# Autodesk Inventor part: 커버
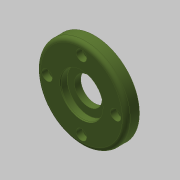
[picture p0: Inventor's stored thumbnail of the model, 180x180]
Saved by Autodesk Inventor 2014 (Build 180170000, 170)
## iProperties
Created: 2016-06
Part Number: 커버
Material: 알루미늄 6061
Document SubType Name: Modeling
Designer: mduedu
Density: 2.71 g/cm^3
Appearance: 올리브 녹색
Author: mduedu
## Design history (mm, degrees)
sketch "스케치1"
  geometry: C1 r 34 at (0, 0); 1 further point
  constraints: 1 centre point, 1 coincident
  dimensions: "d0" = 68 diameter of C1
extrude "돌출1" new body sketch "스케치1" distance "d2" = 10; taper "d3" = 0 deg
sketch "스케치2"
  geometry: C1 r 21 at (0, 0); 1 further point
  constraints: 1 centre point, 1 coincident
  dimensions: "d4" = 42 diameter of C1
extrude "돌출2" join sketch "스케치2" distance "d6" = 3; taper "d7" = 0 deg
fillet "모깎기1" dims "d8" = 3
hole "구멍1" diameter "d11" = 35; stored, may be unused: countersink angle "d15" = 90 deg, drill point angle "d17" = 0 deg; dims "d9" = 10, "d10" = 10, "d12" = 6, "d13" = 4, "d14" = 2, "d16" = 3
hole "구멍2" diameter "d20" = 32; stored, may be unused: countersink angle "d24" = 90 deg, drill point angle "d26" = 0 deg; dims "d21" = 6, "d22" = 4, "d23" = 2, "d25" = 5.2, "d46" = 10, "d47" = 10
hole "구멍3" diameter "d29" = 21; stored, may be unused: countersink angle "d33" = 90 deg, drill point angle "d35" = 0 deg; dims "d27" = 10, "d28" = 10, "d30" = 6, "d31" = 4, "d32" = 2, "d34" = 5
fillet "모깎기2" dims "d36" = 3
fillet "모깎기3" dims "d37" = 0.1
chamfer "모따기1" distance "d38" = 0.75; stored, may be unused: second distance "d39" = 2, angle "d40" = 30 deg
chamfer "모따기2" distance "d42" = 0.5; stored, may be unused: second distance "d43" = 2, angle "d44" = 30 deg
sketch "스케치3" dims "d48" = 52
  geometry: 6 further points
  constraints: 2 vertical alignment, 1 coincident, 7 other
  dimensions: "d51" = 360 deg dimension on point (0, 0) point (0, 26) (derived)
sketch "스케치4"
  geometry: 4 further points
hole "구멍4" sketch "스케치4" at (0, 26), (-26, 0), (0, -26), (26, 0) diameter "d53" = 4.5; stored, may be unused: countersink angle "d57" = 90 deg, drill point angle "d59" = 0 deg; dims "d54" = 6, "d55" = 8, "d56" = 4.6, "d58" = 8
node "솔리드1"
